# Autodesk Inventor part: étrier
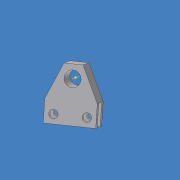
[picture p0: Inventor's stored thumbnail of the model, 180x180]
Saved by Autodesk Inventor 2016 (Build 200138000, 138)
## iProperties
Shininess: 64.0
Length Units: 11269
Angle Units: 11279
Time Units: 11290
Mass Units: 11283
Length Display Precision: 3
Angle Display Precision: 2
Compacted: True
Part Number: étrier
Document SubType Name: Modeling
Created: 2003-07
Material: Générique
Designer: trameau
Density: 1 g/cm^3
Appearance: Par défaut
Density: 0.0
Volumn: 0.0
Area: 0.0
PropertySet Name: Model Information
Control State: 0
Master: False
Checked Out: False
Author: trameau
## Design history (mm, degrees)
sketch "Esquisse1"
  geometry: L1 (-0.06, -6.469)-(-0.06, 56.031); L2 (-0.06, 56.031)-(-10.06, 56.031); L3 (-10.06, 56.031)-(-27.56, 18.531); L4 (-27.56, 18.531)-(-27.56, -6.469); L5 (-27.56, -6.469)-(-0.06, -6.469)
  constraints: 10 end point, 2 parallel, 1 perpendicular, 1 vertical
  dimensions: "d0" = 62.5 distance of L1.start L1.end; "d1" = 25 distance of L3.end L4.end; "d2" = 27.5 distance of L4.end L1.start; "d3" = 10 distance of L1.end L2.end
extrude "Extrusion1" new body sketch "Esquisse1" distance "d4" = 5; taper "d5" = 0 deg
sketch "Esquisse2"
  geometry: L1 (-0.06, 56.031)-(-0.06, -6.469) reference; L2 (-10.06, 56.031)-(-0.06, 56.031) reference; L3 (-27.56, 18.531)-(-10.06, 56.031) reference; L4 (-27.56, -6.469)-(-27.56, 18.531) reference; L5 (-0.06, 18.531)-(-27.56, 18.531)
  constraints: 2 end point, 1 perpendicular, 1 point on line
extrude "Extrusion2" join sketch "Esquisse2" distance "d6" = 5; taper "d7" = 0 deg
mirror "Symétrie1"
mirror "Symétrie2"
sketch "Esquisse3"
  geometry: L1 (37.5, 62.5)-(17.5, 62.5) reference; 1 further point
  dimensions: "d8" = 15 distance from line of L1 point (27.5, 47.5)
hole "Perçage1" sketch "Esquisse3" at (27.5, 47.5) diameter "d9" = 18; stored, may be unused: countersink angle "d13" = 82 deg, drill point angle "d15" = 118 deg; dims "d10" = 6, "d11" = 4, "d12" = 2, "d14" = 8
sketch "Esquisse4"
  geometry: L1 (0, 25)-(0, 0) reference; L2 (55, 0)-(0, 0) reference; L3 (55, 25)-(55, 0) reference; 2 further points
  dimensions: "d16" = 10 distance from line of L2 point (10, 10) (= d17); "d17" = 10 distance from line of L2 point (45, 10); "d18" = 10 distance from line of L3 point (45, 10); "d19" = 10 distance from line of L1 point (10, 10) (= d18)
hole "Perçage2" sketch "Esquisse4" at (10, 10), (45, 10) diameter "d20" = 10; stored, may be unused: countersink angle "d24" = 82 deg, drill point angle "d26" = 118 deg; dims "d21" = 6, "d22" = 4, "d23" = 2, "d25" = 8
node "Plan de construction1"
node "Axe de construction1"
node "Point de construction1"
node "Solide1"
node "Corps solides"
node "Corps surfaciques"
